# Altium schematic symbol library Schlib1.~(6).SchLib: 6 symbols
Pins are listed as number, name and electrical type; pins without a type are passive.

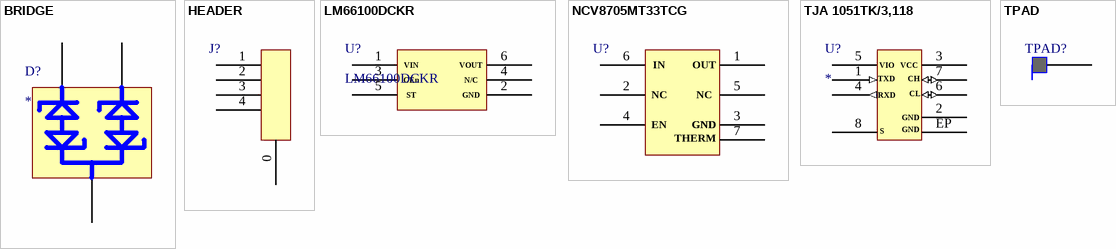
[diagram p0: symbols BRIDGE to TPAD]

## BRIDGE
designator D?
pins: 1, 2, 3

## HEADER
designator J?  (value not drawn)
pins: 0, 1, 2, 3, 4

## LM66100DCKR
designator U?
pins: 1, 2, 3, 4, 5, 6

## NCV8705MT33TCG
designator U?  (value not drawn)
pins: 1, 2, 3, 4, 5, 6, 7

## TJA 1051TK/3,118
designator U?
pins: 1 (in), 2, 3, 4 (out), 5, 6 (io), 7 (io), 8, EP

## TPAD
designator TPAD?  (value not drawn)
pins: 1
